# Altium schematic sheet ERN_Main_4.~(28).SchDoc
size A; SheetNumber: 4; SheetTotal: 4; SPICEModelCacheELVNKBHK: <root> / <DocumentId>ELVNKBHK</DocumentId> / <CacheFrame Number="0"> / <Model Name="led2" Kind="MDL"> / <Text>*Typ RED,GREEN,YELLOW,AMBER GaAs LED: Vf=2.1V Vr=4V If=40mA trr=3uS / *LED Pinout: 1=A, 2=K / .MODEL LED2 D (IS=93.1P RS=42M N=4.61 BV=4 IBV=10U / + CJO=2.97P VJ=.75 M=.333 TT=4.32U)</Text> / </Model> / <Model Name="1n5400" Kind="MDL"> / <Text>*1N5400 MCE / * 50V 3A Si Rectifier pkg:DO-201 1,2 / .MODEL 1N5400 D(IS=2.68E-12 RS=0.00977 N=1.17 TT=1.44E-5 CJO=1.24E-10 / + VJ=0.6 M=0.333 BV=66.6 IBV=1E-5 )</Text> / </Model> / </CacheFrame> / </root>
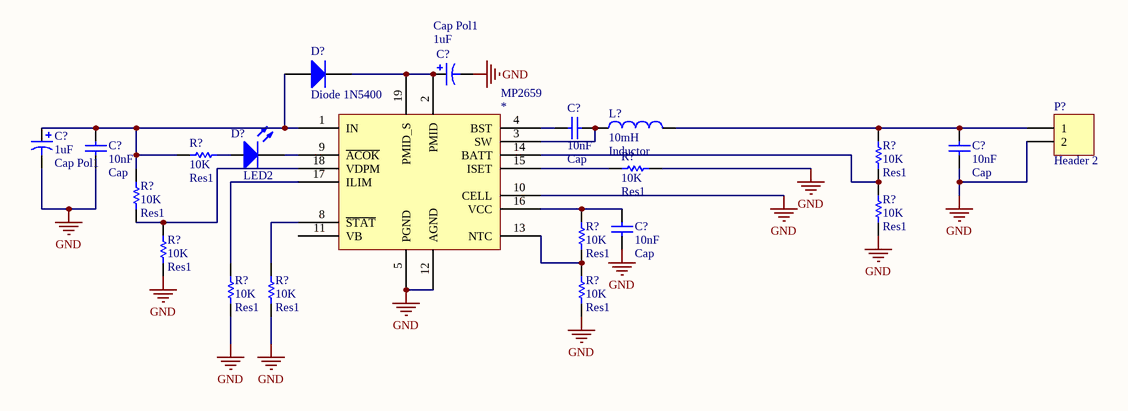
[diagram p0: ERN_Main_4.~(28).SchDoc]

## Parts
(Parts that share a designator on the sheet are numbered #1, #2 ... from top to bottom, then left to right.)
*  MP2659
C?#1  Cap Pol1  value 1uF  [RB7.6-15]
C?#2  Cap Pol1  value 1uF  [RB7.6-15]
C?#3  Cap  value 10nF  [RAD-0.3]
C?#4  Cap  value 10nF  [RAD-0.3]
C?#5  Cap  value 10nF  [RAD-0.3]
C?#6  Cap  value 10nF  [RAD-0.3]
D?#1  Diode 1N5400  [DO-201AD]
D?#2  LED2  [3.2X1.6X1.1]
L?  Inductor  value 10mH  [0402-A]
P?  Header 2  [HDR1X2]
R?#1  Res1  value 10K  [AXIAL-0.3]
R?#2  Res1  value 10K  [AXIAL-0.3]
R?#3  Res1  value 10K  [AXIAL-0.3]
R?#4  Res1  value 10K  [AXIAL-0.3]
R?#5  Res1  value 10K  [AXIAL-0.3]
R?#6  Res1  value 10K  [AXIAL-0.3]
R?#7  Res1  value 10K  [AXIAL-0.3]
R?#8  Res1  value 10K  [AXIAL-0.3]
R?#9  Res1  value 10K  [AXIAL-0.3]
R?#10  Res1  value 10K  [AXIAL-0.3]

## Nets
GND: *.5(PGND) *.10(CELL) *.12(AGND) C?#1.2 C?#2.2 C?#4.2 C?#5.1 C?#6.2 P?.2 R?#1.2 R?#5.1 R?#6.2 R?#8.2 R?#9.2 R?#10.1
Net*_1: *.1(IN) C?#2.1 C?#5.2 D?#1.1(A) R?#2.2 R?#4.1
Net*_2: *.2(PMID) *.19(PMID_S) C?#1.1 D?#1.2(K)
Net*_3: *.3(SW) C?#3.1 L?.1
Net*_4: *.4(BST) C?#3.2
Net*_8: *.8(~{STAT}) R?#9.1
Net*_9: *.9(~{ACOK}) D?#2.2(K)
Net*_13: *.13(NTC) R?#7.1 R?#10.2
Net*_14: *.14(BATT) R?#3.1 R?#5.2
Net*_15: *.15(ISET) R?#1.1
Net*_16: *.16(VCC) C?#6.1 R?#7.2
Net*_17: *.17(ILIM) R?#8.1
Net*_18: *.18(VDPM) R?#4.2 R?#6.1
NetC?#4_1: C?#4.1 L?.2 P?.1 R?#3.2
NetD?#2_1: D?#2.1(A) R?#2.1

Not connected (* = marked no-connect by the designer): * 11(VB)

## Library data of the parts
* = MP2659: 3S-6S Standalone Switching Charger
C?#1 C?#2 = Cap Pol1: Polarized Capacitor (Radial)
C?#3-C?#6 = Cap: Capacitor
D?#1 = Diode 1N5400: 3 Amp General Purpose Rectifier
D?#2 = LED2: Typical RED, GREEN, YELLOW, AMBER GaAs LED
L? = Inductor: Code_IEC: 1005
P? = Header 2: Header, 2-Pin
R?#1-R?#10 = Res1: Resistor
